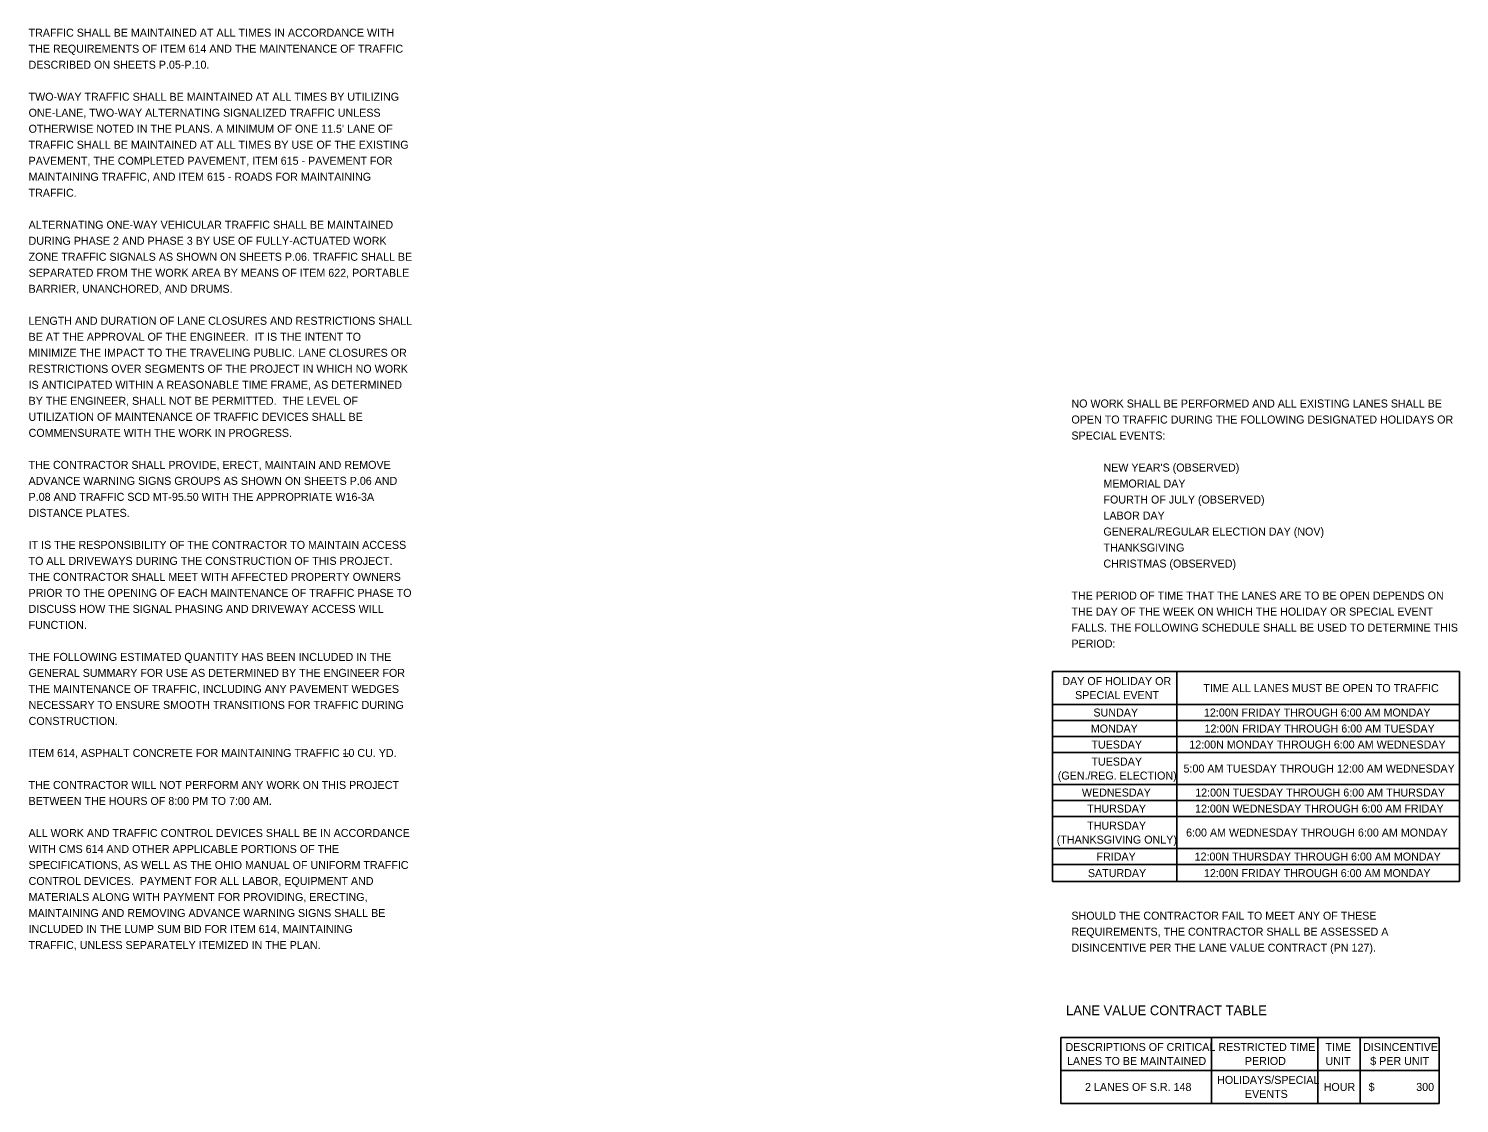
# Model space of a CAD drawing. Extents: x -25.9 to 34, y 0 to 22.
# Drawn here: x -25.92 to -0.89, y 1.27 to 20.07 of the extents above; entities that cross this region are included whole.
import ezdxf

# ---------------------------------------------------------------- set-up
doc = ezdxf.new("R2010")
doc.units = 0
doc.layers.add('SH_Text', color=7, linetype='Continuous')

msp = doc.modelspace()

# ---------------------------------------------------------------- linework, layer by layer
at = {"layer": 'SH_Text'}
for p, q in [((-8.005, 8.82), (-0.89, 8.82)), ((-8.005, 8.82), (-8.005, 5.147)), ((-5.831, 8.82), (-5.831, 5.147)), ((-0.89, 8.82), (-0.89, 5.147)), ((-8.005, 8.244), (-0.89, 8.244)), ((-8.005, 7.964), (-0.89, 7.964)), ((-8.005, 7.684), (-0.89, 7.684)), ((-8.005, 7.404), (-0.89, 7.404)), ((-8.005, 6.844), (-0.89, 6.844)), ((-8.005, 6.564), (-0.89, 6.564)), ((-8.005, 6.284), (-0.89, 6.284)), ((-8.005, 5.724), (-0.89, 5.724)), ((-8.005, 5.444), (-0.89, 5.444)), ((-8.005, 5.147), (-0.89, 5.147)), ((-7.862, 2.419), (-1.241, 2.419)), ((-7.862, 2.419), (-7.862, 1.266)), ((-5.227, 2.419), (-5.227, 1.266)), ((-3.366, 2.419), (-3.366, 1.266)), ((-2.624, 2.419), (-2.624, 1.266)), ((-1.241, 2.419), (-1.241, 1.266)), ((-7.862, 1.843), (-1.241, 1.843)), ((-7.862, 1.266), (-1.241, 1.266))]:
    msp.add_line(p, q, dxfattribs=at)

# ---------------------------------------------------------------- texts
for s, height, p in [('TRAFFIC SHALL BE MAINTAINED AT ALL TIMES IN ACCORDANCE WITH ', 0.14, (-25.918, 19.927)), ('THE REQUIREMENTS OF ITEM 614 AND THE MAINTENANCE OF TRAFFIC ', 0.14, (-25.918, 19.647)), ('DESCRIBED ON SHEETS P.05-P.10.', 0.14, (-25.918, 19.367)), ('TWO-WAY TRAFFIC SHALL BE MAINTAINED AT ALL TIMES BY UTILIZING ', 0.14, (-25.918, 18.807)), ('ONE-LANE, TWO-WAY ALTERNATING SIGNALIZED TRAFFIC UNLESS ', 0.14, (-25.918, 18.527)), ("OTHERWISE NOTED IN THE PLANS. A MINIMUM OF ONE 11.5' LANE OF ", 0.14, (-25.918, 18.247)), ('TRAFFIC SHALL BE MAINTAINED AT ALL TIMES BY USE OF THE EXISTING ', 0.14, (-25.918, 17.967)), ('PAVEMENT, THE COMPLETED PAVEMENT, ITEM 615 - PAVEMENT FOR ', 0.14, (-25.918, 17.687)), ('MAINTAINING TRAFFIC, AND ITEM 615 - ROADS FOR MAINTAINING ', 0.14, (-25.918, 17.407)), ('TRAFFIC.', 0.14, (-25.918, 17.127)), ('ALTERNATING ONE-WAY VEHICULAR TRAFFIC SHALL BE MAINTAINED ', 0.14, (-25.918, 16.567)), ('DURING PHASE 2 AND PHASE 3 BY USE OF FULLY-ACTUATED WORK ', 0.14, (-25.918, 16.287)), ('ZONE TRAFFIC SIGNALS AS SHOWN ON SHEETS P.06. TRAFFIC SHALL BE ', 0.14, (-25.918, 16.007)), ('SEPARATED FROM THE WORK AREA BY MEANS OF ITEM 622, PORTABLE ', 0.14, (-25.918, 15.727)), ('BARRIER, UNANCHORED, AND DRUMS.', 0.14, (-25.918, 15.447)), ('LENGTH AND DURATION OF LANE CLOSURES AND RESTRICTIONS SHALL ', 0.14, (-25.918, 14.887)), ('BE AT THE APPROVAL OF THE ENGINEER.  IT IS THE INTENT TO ', 0.14, (-25.918, 14.607)), ('MINIMIZE THE IMPACT TO THE TRAVELING PUBLIC. LANE CLOSURES OR ', 0.14, (-25.918, 14.327)), ('RESTRICTIONS OVER SEGMENTS OF THE PROJECT IN WHICH NO WORK ', 0.14, (-25.918, 14.047)), ('IS ANTICIPATED WITHIN A REASONABLE TIME FRAME, AS DETERMINED ', 0.14, (-25.918, 13.767)), ('BY THE ENGINEER, SHALL NOT BE PERMITTED.  THE LEVEL OF ', 0.14, (-25.918, 13.487)), ('NO WORK SHALL BE PERFORMED AND ALL EXISTING LANES SHALL BE ', 0.14, (-7.676, 13.44)), ('UTILIZATION OF MAINTENANCE OF TRAFFIC DEVICES SHALL BE ', 0.14, (-25.918, 13.207)), ('OPEN TO TRAFFIC DURING THE FOLLOWING DESIGNATED HOLIDAYS OR ', 0.14, (-7.676, 13.16)), ('COMMENSURATE WITH THE WORK IN PROGRESS.', 0.14, (-25.918, 12.927)), ('SPECIAL EVENTS:', 0.14, (-7.676, 12.88)), ('THE CONTRACTOR SHALL PROVIDE, ERECT, MAINTAIN AND REMOVE ', 0.14, (-25.918, 12.367)), ("NEW YEAR'S (OBSERVED)", 0.14, (-7.116, 12.32)), ('ADVANCE WARNING SIGNS GROUPS AS SHOWN ON SHEETS P.06 AND ', 0.14, (-25.918, 12.087)), ('MEMORIAL DAY', 0.14, (-7.116, 12.04)), ('P.08 AND TRAFFIC SCD MT-95.50 WITH THE APPROPRIATE W16-3A ', 0.14, (-25.918, 11.807)), ('FOURTH OF JULY (OBSERVED)', 0.14, (-7.116, 11.76)), ('DISTANCE PLATES. ', 0.14, (-25.918, 11.527)), ('LABOR DAY', 0.14, (-7.116, 11.48)), ('GENERAL/REGULAR ELECTION DAY (NOV)', 0.14, (-7.116, 11.2)), ('IT IS THE RESPONSIBILITY OF THE CONTRACTOR TO MAINTAIN ACCESS ', 0.14, (-25.918, 10.967)), ('THANKSGIVING', 0.14, (-7.116, 10.92)), ('TO ALL DRIVEWAYS DURING THE CONSTRUCTION OF THIS PROJECT.  ', 0.14, (-25.918, 10.687)), ('CHRISTMAS (OBSERVED)', 0.14, (-7.116, 10.64)), ('THE CONTRACTOR SHALL MEET WITH AFFECTED PROPERTY OWNERS ', 0.14, (-25.918, 10.407)), ('PRIOR TO THE OPENING OF EACH MAINTENANCE OF TRAFFIC PHASE TO ', 0.14, (-25.918, 10.127)), ('THE PERIOD OF TIME THAT THE LANES ARE TO BE OPEN DEPENDS ON ', 0.14, (-7.676, 10.08)), ('DISCUSS HOW THE SIGNAL PHASING AND DRIVEWAY ACCESS WILL ', 0.14, (-25.918, 9.847)), ('THE DAY OF THE WEEK ON WHICH THE HOLIDAY OR SPECIAL EVENT ', 0.14, (-7.676, 9.8)), ('FUNCTION.', 0.14, (-25.918, 9.567)), ('FALLS. THE FOLLOWING SCHEDULE SHALL BE USED TO DETERMINE THIS ', 0.14, (-7.676, 9.52)), ('PERIOD:', 0.14, (-7.676, 9.24)), ('THE FOLLOWING ESTIMATED QUANTITY HAS BEEN INCLUDED IN THE ', 0.14, (-25.918, 9.007)), ('GENERAL SUMMARY FOR USE AS DETERMINED BY THE ENGINEER FOR ', 0.14, (-25.918, 8.727)), ('THE MAINTENANCE OF TRAFFIC, INCLUDING ANY PAVEMENT WEDGES ', 0.14, (-25.918, 8.447)), ('DAY OF HOLIDAY OR', 0.14, (-7.835, 8.584)), ('TIME ALL LANES MUST BE OPEN TO TRAFFIC', 0.14, (-5.369, 8.462)), ('NECESSARY TO ENSURE SMOOTH TRANSITIONS FOR TRAFFIC DURING ', 0.14, (-25.918, 8.167)), ('SPECIAL EVENT', 0.14, (-7.612, 8.339)), ('CONSTRUCTION.', 0.14, (-25.918, 7.887)), ('SUNDAY', 0.14, (-7.291, 8.034)), ('12:00N FRIDAY THROUGH 6:00 AM MONDAY', 0.14, (-5.358, 8.034)), ('MONDAY', 0.14, (-7.337, 7.754)), ('12:00N FRIDAY THROUGH 6:00 AM TUESDAY', 0.14, (-5.348, 7.754)), ('TUESDAY', 0.14, (-7.326, 7.474)), ('12:00N MONDAY THROUGH 6:00 AM WEDNESDAY', 0.14, (-5.614, 7.474)), ('ITEM 614, ASPHALT CONCRETE FOR MAINTAINING TRAFFIC -- ', 0.14, (-25.918, 7.327)), ('10 CU. YD.', 0.14, (-20.427, 7.327)), ('TUESDAY', 0.14, (-7.326, 7.176)), ('(GEN./REG. ELECTION)', 0.14, (-7.915, 6.931)), ('5:00 AM TUESDAY THROUGH 12:00 AM WEDNESDAY', 0.14, (-5.715, 7.054)), ('THE CONTRACTOR WILL NOT PERFORM ANY WORK ON THIS PROJECT ', 0.14, (-25.918, 6.767)), ('WEDNESDAY', 0.14, (-7.493, 6.634)), ('12:00N TUESDAY THROUGH 6:00 AM THURSDAY', 0.14, (-5.511, 6.634)), ('BETWEEN THE HOURS OF 8:00 PM TO 7:00 AM.', 0.14, (-25.918, 6.487)), ('THURSDAY', 0.14, (-7.401, 6.354)), ('12:00N WEDNESDAY THROUGH 6:00 AM FRIDAY', 0.14, (-5.514, 6.354)), ('ALL WORK AND TRAFFIC CONTROL DEVICES SHALL BE IN ACCORDANCE ', 0.14, (-25.918, 5.927)), ('THURSDAY', 0.14, (-7.401, 6.056)), ('6:00 AM WEDNESDAY THROUGH 6:00 AM MONDAY', 0.14, (-5.67, 5.934)), ('WITH CMS 614 AND OTHER APPLICABLE PORTIONS OF THE ', 0.14, (-25.918, 5.647)), ('(THANKSGIVING ONLY)', 0.14, (-7.932, 5.811)), ('SPECIFICATIONS, AS WELL AS THE OHIO MANUAL OF UNIFORM TRAFFIC ', 0.14, (-25.918, 5.367)), ('FRIDAY', 0.14, (-7.238, 5.514)), ('12:00N THURSDAY THROUGH 6:00 AM MONDAY', 0.14, (-5.521, 5.514)), ('SATURDAY', 0.14, (-7.388, 5.225)), ('12:00N FRIDAY THROUGH 6:00 AM MONDAY', 0.14, (-5.358, 5.225)), ('CONTROL DEVICES.  PAYMENT FOR ALL LABOR, EQUIPMENT AND ', 0.14, (-25.918, 5.087)), ('MATERIALS ALONG WITH PAYMENT FOR PROVIDING, ERECTING, ', 0.14, (-25.918, 4.807)), ('MAINTAINING AND REMOVING ADVANCE WARNING SIGNS SHALL BE ', 0.14, (-25.918, 4.527)), ('SHOULD THE CONTRACTOR FAIL TO MEET ANY OF THESE ', 0.14, (-7.676, 4.48)), ('INCLUDED IN THE LUMP SUM BID FOR ITEM 614, MAINTAINING ', 0.14, (-25.918, 4.247)), ('REQUIREMENTS, THE CONTRACTOR SHALL BE ASSESSED A ', 0.14, (-7.676, 4.2)), ('TRAFFIC, UNLESS SEPARATELY ITEMIZED IN THE PLAN.', 0.14, (-25.918, 3.967)), ('DISINCENTIVE PER THE LANE VALUE CONTRACT (PN 127).', 0.14, (-7.676, 3.92)), ('LANE VALUE CONTRACT TABLE', 0.17, (-7.77, 2.809)), ('DESCRIPTIONS OF CRITICAL ', 0.14, (-7.78, 2.183)), ('RESTRICTED TIME ', 0.14, (-5.105, 2.183)), ('TIME ', 0.14, (-3.232, 2.183)), ('DISINCENTIVE ', 0.14, (-2.574, 2.183)), ('LANES TO BE MAINTAINED', 0.14, (-7.754, 1.938)), ('PERIOD', 0.14, (-4.642, 1.938)), ('UNIT', 0.14, (-3.231, 1.938)), ('$ PER UNIT', 0.14, (-2.449, 1.938)), ('HOLIDAYS/SPECIAL ', 0.14, (-5.127, 1.607)), ('2 LANES OF S.R. 148', 0.14, (-7.439, 1.484)), ('EVENTS', 0.14, (-4.641, 1.362)), ('HOUR', 0.14, (-3.264, 1.484)), (' $              300', 0.14, (-2.529, 1.484))]:
    msp.add_text(s, height=height, dxfattribs=at).set_placement(p)

doc.saveas('drawing.dxf')
